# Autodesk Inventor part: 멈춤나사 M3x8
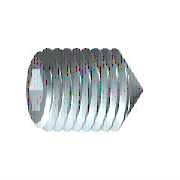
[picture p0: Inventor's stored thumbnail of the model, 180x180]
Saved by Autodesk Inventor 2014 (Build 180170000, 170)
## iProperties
IsCustomPart: 1
Created: 2012-02
Part Number: 멈춤나사 M3x8
Material: 강철, 연강
Description: 6각 소켓 머리 없는 멈춤 나사
Document SubType Name: Modeling
Standard: KS B 1028
Designer: test
Standards Organization: KS
Language: ko-KR
Size Designation: 원추점 M3x8
Categories: <MemberInstance><Categories><Category DisplayName="조임쇠" InternalName="e4da775c-781d-43d5-af7c-5136215cf5a6" Mnemonic="FSTN"><Category DisplayName="볼트" InternalN
Density: 1 g/cm^3
Appearance: 강철
Author: test
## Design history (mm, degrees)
sketch "스케치1"
  geometry: L1 (0, 0)-(5.5, 0); L2 (8, 0.866)-(8, 1.5); L3 (8, 1.5)-(0, 1.5); L4 (8, 0.866)-(6, 0.866); L5 (6, 0.866)-(5.5, 0); L6 (0, -0.3)-(0, 1.8) reference; L7 (0, 1.5)-(0, 0)
  constraints: 13 end point, 3 parallel, 1 collinear, 1 perpendicular, 1 point on line
  dimensions: "d0" = 2 distance of L2.start L4.end (= INTI); "d1" = 60 deg angle of L5 L1; "d2" = 3 diameter of L3 L1 (= NND); "d3" = 1.73205 diameter of L4 L1 (= 1.1547 x SW); "d5" = 8 distance from line of L2 L3.end (= NLG)
revolve "본체" sketch "스케치1" stored, may be unused: angle "d6" = 90 deg
sketch "스케치2"
  geometry: L1 (-0.433, 0.75)-(0.433, 0.75); L2 (0.433, 0.75)-(0.866, 0); L3 (0.866, 0)-(0.433, -0.75); L4 (0.433, -0.75)-(-0.433, -0.75); L5 (-0.433, -0.75)-(-0.866, 0); L6 (-0.866, 0)-(-0.433, 0.75); 3 further points
  constraints: 12 end point, 1 coincident, 1 horizontal, 13 other
extrude "슬롯" join sketch "스케치2" taper "d7" = 0 deg; stored distance "d21" = 10
workaxis "Work Axis1"
workplane "Work Plane1"
sketch "스케치4"
  geometry: L1 (0, 0.15)-(-1.35, 1.5) reference; L2 (0, -0.15)-(-1.35, -1.5) reference; L3 (-1.35, -1.5)-(0.15, 0); L4 (-1.35, 1.5)-(0.15, 0); 2 further points
  constraints: 4 end point, 1 coincident, 1 collinear, 1 horizontal alignment
body "Solid1"
feature "스레드" dims "d12" = 8 (= NLG), "d13" = 0
chamfer "모따기1" distance "d8" = 1.35 (computed from NND, SPD, FAWI); stored, may be unused: angle "d9" = 45 deg (= FAWI), second distance "d34" = 1.35 (computed from NND, SPD, FAWI)
chamfer "모따기2" distance "d10" = 0.30673 (= -0.5 x GD1 + 0.5 x NND); stored, may be unused: angle "d11" = 45 deg (= FAWI), second distance "d35" = 0.30673 (= -0.5 x GD1 + 0.5 x NND)
other parameters: "NND" = 3 [user parameter; used in 5 equation terms], "NLG" = 8 [user parameter; used in 2 equation terms], "INTI" = 2 [user parameter; used in 1 equation term], "FAWI" = 45 deg [user parameter; used in 4 equation terms], "SW" = 1.5 [user parameter; used in 2 equation terms], "GD1" = 2.38655 (= THREADDIA - 1.2269 x PTC) [user parameter; used in 2 equation terms], "d4" = 0, "FAWI1" = 45 deg [user parameter], "SPD" = 0.3 [user parameter; used in 2 equation terms], "d36" = 0, "d37" = 0, "GUL" = 0.30673 (= 0.61345 x PTC) [user parameter], "TOA" = 30 deg [user parameter], "THREADDIA" = 3 [user parameter; used in 1 equation term], "PTC" = 0.5 [user parameter; used in 4 equation terms], "GAL" = 0.30673 (= 0.61345 x PTC) [user parameter], "E0" = 1.7325 (= 1.155 x SW) [user parameter]
